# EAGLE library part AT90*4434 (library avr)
MICROCONTROLLER Low-voltage (LS) 4 Kbytes FLASH 256 bytes SRAM 256 bytes EEPROM UART 8-channel 10 bit ADC
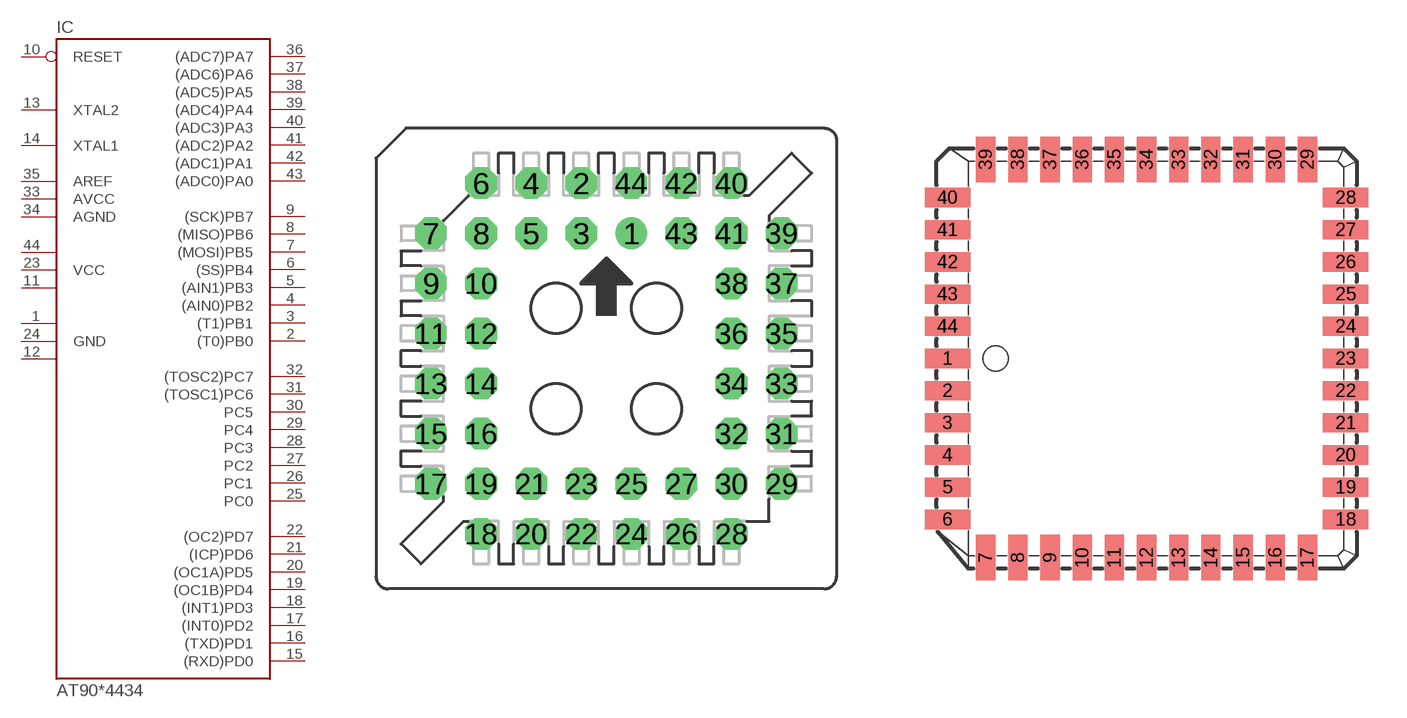
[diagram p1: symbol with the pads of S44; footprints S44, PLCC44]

Designator prefix IC

## AT90LS4434J-S, AT90S4434J-S  [S44]
1  GND1  pwr
2  (T0)PB0
3  (T1)PB1
4  (AIN0)PB2
5  (AIN1)PB3
6  (SS)PB4
7  (MOSI)PB5
8  (MISO)PB6
9  (SCK)PB7
10  RESET  in
11  VCC2  pwr
12  GND2  pwr
13  XTAL2
14  XTAL1
15  (RXD)PD0
16  (TXD)PD1
17  (INT0)PD2
18  (INT1)PD3
19  (OC1B)PD4
20  (OC1A)PD5
21  (ICP)PD6
22  (OC2)PD7
23  VCC  pwr
24  GND  pwr
25  PC0
26  PC1
27  PC2
28  PC3
29  PC4
30  PC5
31  (TOSC1)PC6
32  (TOSC2)PC7
33  AVCC  pwr
34  AGND  pwr
35  AREF  pwr
36  (ADC7)PA7
37  (ADC6)PA6
38  (ADC5)PA5
39  (ADC4)PA4
40  (ADC3)PA3
41  (ADC2)PA2
42  (ADC1)PA1
43  (ADC0)PA0
44  VCC1  pwr

## AT90LS4434J, AT90S4434J  [PLCC44]
1  GND1  pwr
2  (T0)PB0
3  (T1)PB1
4  (AIN0)PB2
5  (AIN1)PB3
6  (SS)PB4
7  (MOSI)PB5
8  (MISO)PB6
9  (SCK)PB7
10  RESET  in
11  VCC1  pwr
12  GND2  pwr
13  XTAL2
14  XTAL1
15  (RXD)PD0
16  (TXD)PD1
17  (INT0)PD2
18  (INT1)PD3
19  (OC1B)PD4
20  (OC1A)PD5
21  (ICP)PD6
22  (OC2)PD7
23  VCC  pwr
24  GND  pwr
25  PC0
26  PC1
27  PC2
28  PC3
29  PC4
30  PC5
31  (TOSC1)PC6
32  (TOSC2)PC7
33  AVCC  pwr
34  AGND  pwr
35  AREF  pwr
36  (ADC7)PA7
37  (ADC6)PA6
38  (ADC5)PA5
39  (ADC4)PA4
40  (ADC3)PA3
41  (ADC2)PA2
42  (ADC1)PA1
43  (ADC0)PA0
44  VCC2  pwr

## AT90LS4434J-SM, AT90S4434J-SM  [PLCC-SM44]
Pads as for PLCC44

## AT904434A  [TQFP44]
1  (MOSI)PB5
2  (MISO)PB6
3  (SCK)PB7
4  RESET  in
5  VCC  pwr
6  GND  pwr
7  XTAL2
8  XTAL1
9  (RXD)PD0
10  (TXD)PD1
11  (INT0)PD2
12  (INT1)PD3
13  (OC1B)PD4
14  (OC1A)PD5
15  (ICP)PD6
16  (OC2)PD7
17  VCC1  pwr
18  GND1  pwr
19  PC0
20  PC1
21  PC2
22  PC3
23  PC4
24  PC5
25  (TOSC1)PC6
26  (TOSC2)PC7
27  AVCC  pwr
28  AGND  pwr
29  AREF  pwr
30  (ADC7)PA7
31  (ADC6)PA6
32  (ADC5)PA5
33  (ADC4)PA4
34  (ADC3)PA3
35  (ADC2)PA2
36  (ADC1)PA1
37  (ADC0)PA0
38  VCC2  pwr
39  GND2  pwr
40  (T0)PB0
41  (T1)PB1
42  (AIN0)PB2
43  (AIN1)PB3
44  (SS)PB4

## Footprint S44 (pad centres in mm)
Throughhole Plastic J-Leaded Chip Carrier Socket
drill 0.813 pad 1.6 round: 1 1.27,6.35
drill 0.813 pad 1.6 octagon: 2 -1.27,8.89; 3 -1.27,6.35; 4 -3.81,8.89; 5 -3.81,6.35; 6 -6.35,8.89; 7 -8.89,6.35; 8 -6.35,6.35; 9 -8.89,3.81; 10 -6.35,3.81; 11 -8.89,1.27; 12 -6.35,1.27; 13 -8.89,-1.27; 14 -6.35,-1.27; 15 -8.89,-3.81; 16 -6.35,-3.81; 17 -8.89,-6.35; 18 -6.35,-8.89; 19 -6.35,-6.35; 20 -3.81,-8.89; 21 -3.81,-6.35; 22 -1.27,-8.89; 23 -1.27,-6.35; 24 1.27,-8.89; 25 1.27,-6.35; 26 3.81,-8.89; 27 3.81,-6.35; 28 6.35,-8.89; 29 8.89,-6.35; 30 6.35,-6.35; 31 8.89,-3.81; 32 6.35,-3.81; 33 8.89,-1.27; 34 6.35,-1.27; 35 8.89,1.27; 36 6.35,1.27; 37 8.89,3.81; 38 6.35,3.81; 39 8.89,6.35; 40 6.35,8.89; 41 6.35,6.35; 42 3.81,8.89; 43 3.81,6.35; 44 1.27,8.89

## Footprint PLCC44 (pad centres in mm)
Plastic J-Leaded Chip Carrier
smd 1.8 x 0.76: 1 -7.86,0; 2 -7.86,-1.27; 3 -7.86,-2.54; 4 -7.86,-3.81; 5 -7.86,-5.08; 6 -7.86,-6.35; 18 7.86,-6.35; 19 7.86,-5.08; 20 7.86,-3.81; 21 7.86,-2.54; 22 7.86,-1.27; 23 7.86,0; 24 7.86,1.27; 25 7.86,2.54; 26 7.86,3.81; 27 7.86,5.08; 28 7.86,6.35; 40 -7.86,6.35; 41 -7.86,5.08; 42 -7.86,3.81; 43 -7.86,2.54; 44 -7.86,1.27
smd 0.76 x 1.8: 7 -6.35,-7.86; 8 -5.08,-7.86; 9 -3.81,-7.86; 10 -2.54,-7.86; 11 -1.27,-7.86; 12 0,-7.86; 13 1.27,-7.86; 14 2.54,-7.86; 15 3.81,-7.86; 16 5.08,-7.86; 17 6.35,-7.86; 29 6.35,7.86; 30 5.08,7.86; 31 3.81,7.86; 32 2.54,7.86; 33 1.27,7.86; 34 0,7.86; 35 -1.27,7.86; 36 -2.54,7.86; 37 -3.81,7.86; 38 -5.08,7.86; 39 -6.35,7.86

## Footprint PLCC-SM44 (pad centres in mm)
SMD Plastic J-Leaded Chip Carrier Socket
smd 2.591 x 0.66: 1 -8.89,0; 2 -8.89,-1.27; 3 -8.89,-2.54; 4 -8.89,-3.81; 5 -8.89,-5.08; 6 -8.89,-6.35; 18 8.89,-6.35; 19 8.89,-5.08; 20 8.89,-3.81; 21 8.89,-2.54; 22 8.89,-1.27; 23 8.89,0; 24 8.89,1.27; 25 8.89,2.54; 26 8.89,3.81; 27 8.89,5.08; 28 8.89,6.35; 40 -8.89,6.35; 41 -8.89,5.08; 42 -8.89,3.81; 43 -8.89,2.54; 44 -8.89,1.27
smd 0.66 x 2.591: 7 -6.35,-8.89; 8 -5.08,-8.89; 9 -3.81,-8.89; 10 -2.54,-8.89; 11 -1.27,-8.89; 12 0,-8.89; 13 1.27,-8.89; 14 2.54,-8.89; 15 3.81,-8.89; 16 5.08,-8.89; 17 6.35,-8.89; 29 6.35,8.89; 30 5.08,8.89; 31 3.81,8.89; 32 2.54,8.89; 33 1.27,8.89; 34 0,9.017; 35 -1.27,8.89; 36 -2.54,8.89; 37 -3.81,8.89; 38 -5.08,8.89; 39 -6.35,8.89

## Footprint TQFP44 (pad centres in mm)
Thin Plasic Quad Flat Package
smd 1.5 x 0.5: 1 -5.8,4; 2 -5.8,3.2; 3 -5.8,2.4; 4 -5.8,1.6; 5 -5.8,0.8; 6 -5.8,0; 7 -5.8,-0.8; 8 -5.8,-1.6; 9 -5.8,-2.4; 10 -5.8,-3.2; 11 -5.8,-4; 23 5.8,-4; 24 5.8,-3.2; 25 5.8,-2.4; 26 5.8,-1.6; 27 5.8,-0.8; 28 5.8,0; 29 5.8,0.8; 30 5.8,1.6; 31 5.8,2.4; 32 5.8,3.2; 33 5.8,4
smd 0.5 x 1.5: 12 -4,-5.8; 13 -3.2,-5.8; 14 -2.4,-5.8; 15 -1.6,-5.8; 16 -0.8,-5.8; 17 0,-5.8; 18 0.8,-5.8; 19 1.6,-5.8; 20 2.4,-5.8; 21 3.2,-5.8; 22 4,-5.8; 34 4,5.8; 35 3.2,5.8; 36 2.4,5.8; 37 1.6,5.8; 38 0.8,5.8; 39 0,5.8; 40 -0.8,5.8; 41 -1.6,5.8; 42 -2.4,5.8; 43 -3.2,5.8; 44 -4,5.8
